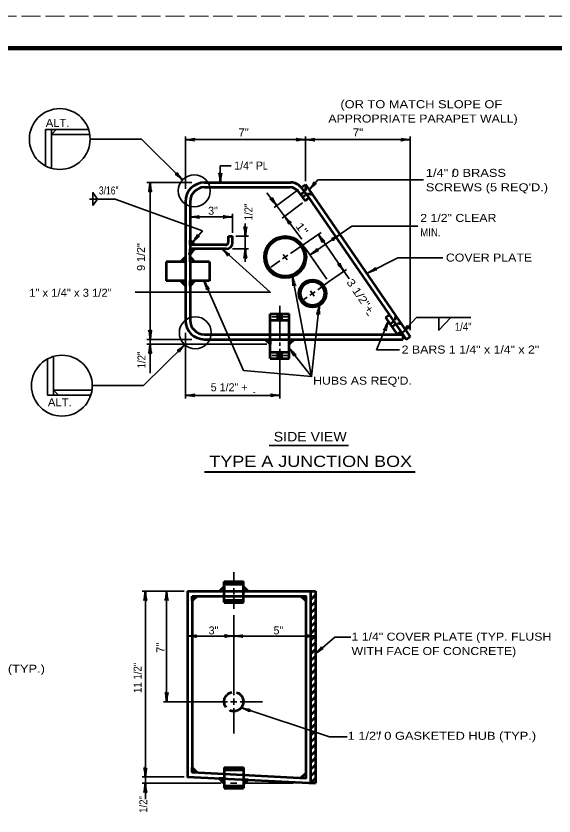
# Model space of a CAD drawing. Extents: x -1 to 679, y 0 to 440.
# Drawn here: x 229.6 to 397.8, y 190.4 to 440.4 of the extents above; entities that cross this region are included whole.
import ezdxf
from ezdxf.enums import TextEntityAlignment as Align

# ---------------------------------------------------------------- set-up
doc = ezdxf.new("R2010")
doc.units = 0
doc.header["$PDMODE"] = 32
doc.header["$PDSIZE"] = 0.5
doc.linetypes.add('LONG_DASHED', pattern=[7.5, 6, -1.5])
doc.linetypes.add('SHORT_DASHED', pattern=[2.7, 1.5, -1.2])
doc.layers.add('1', color=7, linetype='Continuous', lineweight=53)
doc.layers.add('61', color=7, linetype='Continuous', lineweight=35)

msp = doc.modelspace()

# ---------------------------------------------------------------- linework, layer by layer
at = {"layer": '1', "lineweight": 35}
for p, q in [((238.782, 404.893), (238.782, 393.562)), ((240.64, 404.893), (238.782, 404.893)), ((252.64, 403.393), (240.64, 403.393)), ((282.515, 386.364), (282.515, 402.759)), ((320.065, 388.759), (320.065, 402.759)), ((352.823, 342.25), (352.823, 402.759)), ((284.515, 388.364), (270.515, 388.364)), ((271.515, 388.364), (271.515, 339.364)), ((310.24, 380.571), (317.908, 386.18)), ((312.741, 377.253), (319.129, 382.067)), ((297.265, 377.614), (284.015, 377.614)), ((297.265, 372.614), (297.265, 378.614)), ((284.711, 369.667), (287.846, 373.294)), ((315.384, 366.197), (324.923, 372.761)), ((321.502, 365.743), (334.578, 374.741)), ((334.578, 374.741), (355.163, 374.741)), ((298.265, 371.614), (302.265, 371.614)), ((324.099, 372.195), (333.707, 358.234)), ((297.265, 367.614), (302.265, 367.614)), ((319.89, 368.084), (326.726, 358.152)), ((312.913, 364.496), (314.56, 365.63)), ((314.346, 364.254), (313.135, 365.862)), ((309.221, 361.956), (312.089, 363.93)), ((327.293, 357.328), (332.892, 361.181)), ((321.951, 327.71), (316.014, 358.975)), ((323.883, 354.848), (327.293, 357.328)), ((319.593, 351.858), (320.606, 352.555)), ((321.429, 353.122), (323.077, 354.256)), ((322.82, 352.865), (321.686, 354.513)), ((321.951, 327.71), (324.353, 349.989)), ((312.015, 339.364), (312.015, 349.864)), ((309.515, 346.364), (314.515, 346.364)), ((311.015, 346.864), (313.015, 346.864)), ((311.015, 345.864), (313.015, 345.864)), ((350.235, 341.27), (354.799, 346.197)), ((354.799, 346.197), (371.799, 346.197)), ((282.515, 341.364), (282.515, 320.864)), ((282.333, 337.658), (269.457, 324.936)), ((284.515, 339.364), (270.515, 339.364)), ((308.015, 337.864), (270.515, 337.864)), ((312.015, 337.364), (312.015, 338.364)), ((312.015, 320.864), (312.015, 336.364)), ((239.455, 321.936), (239.455, 333.267)), ((309.515, 334.364), (314.515, 334.364)), ((310.015, 333.364), (314.015, 333.364)), ((311.015, 334.864), (313.015, 334.864)), ((311.015, 333.864), (313.015, 333.864)), ((253.313, 323.436), (241.313, 323.436)), ((269.457, 324.936), (253.457, 324.936)), ((241.313, 321.936), (239.455, 321.936)), ((282.515, 321.864), (312.015, 321.864)), ((308.726, 306.159), (333.493, 306.159)), ((297.66, 266.653), (297.66, 262.637)), ((282.16, 260.653), (269.007, 260.653)), ((276.655, 226.153), (276.655, 260.653)), ((297.66, 261.653), (297.66, 259.653)), ((297.66, 258.679), (297.66, 255.153)), ((297.66, 253.153), (297.66, 228.175)), ((297.66, 246.653), (283.16, 246.653)), ((297.66, 246.653), (323.16, 246.653)), ((295.655, 226.153), (275.655, 226.153)), ((298.66, 226.153), (296.66, 226.153)), ((297.66, 227.153), (297.66, 225.153)), ((306.655, 226.153), (299.655, 226.153)), ((297.66, 224.175), (297.66, 216.175)), ((282.16, 202.653), (269.007, 202.653)), ((293.66, 200.653), (269.007, 200.653)), ((298.66, 200.653), (296.66, 200.653)), ((316.306, 200.653), (301.66, 200.653))]:
    msp.add_line(p, q, dxfattribs=at)
at = {"layer": '1'}
for p, q in [((288.515, 388.364), (315.52, 388.364)), ((318.715, 386.771), (320.065, 387.759)), ((320.065, 387.759), (352.804, 340.182)), ((288.515, 386.864), (315.271, 386.864)), ((317.667, 385.669), (319.928, 382.669)), ((318.715, 386.771), (321.126, 383.572)), ((319.928, 382.669), (321.126, 383.572)), ((321.126, 383.572), (350.515, 340.864)), ((282.515, 382.364), (282.515, 366.114)), ((296.015, 369.864), (296.015, 371.614)), ((296.015, 371.614), (297.265, 371.614)), ((297.265, 369.614), (297.265, 371.614)), ((295.015, 368.864), (284.015, 368.864)), ((295.265, 367.614), (284.015, 367.614)), ((284.015, 363.614), (284.015, 367.614)), ((282.515, 366.114), (282.515, 363.614)), ((282.515, 363.614), (276.515, 363.614)), ((276.515, 363.614), (276.515, 357.614)), ((282.515, 364.781), (282.515, 364.614)), ((282.515, 363.614), (282.515, 357.614)), ((284.015, 364.614), (284.015, 364.897)), ((290.015, 363.614), (284.015, 363.614)), ((284.015, 363.614), (284.015, 357.614)), ((290.015, 363.614), (290.015, 357.614)), ((282.515, 357.614), (276.515, 357.614)), ((282.515, 357.614), (282.515, 345.364)), ((290.015, 357.614), (284.015, 357.614)), ((309.015, 347.364), (315.015, 347.364)), ((309.015, 340.864), (309.015, 347.364)), ((309.015, 345.364), (315.015, 345.364)), ((345.048, 346.161), (346.248, 347.065)), ((345.048, 346.161), (348.694, 340.864)), ((288.515, 340.864), (350.515, 340.864)), ((350.515, 340.864), (350.515, 339.364)), ((350.515, 340.864), (351.569, 339.332)), ((351.569, 339.332), (352.823, 340.25)), ((318.962, 339.364), (350.515, 339.364)), ((309.015, 335.364), (315.015, 335.364)), ((309.015, 333.364), (315.015, 333.364)), ((294.66, 263.653), (300.66, 263.653)), ((294.66, 262.903), (300.66, 262.903)), ((300.66, 260.653), (300.66, 263.653)), ((321.66, 260.125), (322.188, 260.653)), ((323.16, 260.653), (323.16, 200.653)), ((284.66, 259.153), (320.16, 259.153)), ((284.66, 259.153), (284.66, 204.079)), ((294.66, 257.903), (300.66, 257.903)), ((320.16, 259.153), (320.16, 202.304)), ((321.66, 258.003), (323.16, 259.503)), ((294.66, 257.153), (300.66, 257.153)), ((321.66, 255.882), (323.16, 257.382)), ((321.66, 253.761), (323.16, 255.261)), ((321.66, 251.639), (323.16, 253.139)), ((321.66, 249.518), (323.16, 251.018)), ((321.66, 247.397), (323.16, 248.897)), ((321.66, 245.275), (323.16, 246.775)), ((321.66, 243.154), (323.16, 244.654)), ((321.66, 241.033), (323.16, 242.533)), ((321.66, 238.911), (323.16, 240.411)), ((321.66, 236.79), (323.16, 238.29)), ((321.66, 234.669), (323.16, 236.169)), ((321.66, 232.547), (323.16, 234.047)), ((321.66, 230.426), (323.16, 231.926)), ((321.66, 228.305), (323.16, 229.805)), ((321.66, 226.183), (323.16, 227.683)), ((321.66, 224.062), (323.16, 225.562)), ((321.66, 221.941), (323.16, 223.441)), ((321.66, 219.82), (323.16, 221.32)), ((321.66, 217.698), (323.16, 219.198)), ((321.66, 215.577), (323.16, 217.077)), ((321.66, 213.456), (323.16, 214.956)), ((321.66, 211.334), (323.16, 212.834)), ((321.66, 209.213), (323.16, 210.713)), ((321.66, 207.092), (323.16, 208.592)), ((294.66, 205.592), (300.66, 205.592)), ((321.66, 204.97), (323.16, 206.47)), ((284.66, 204.079), (320.16, 202.304)), ((294.66, 204.842), (300.66, 204.842)), ((321.66, 202.849), (323.16, 204.349)), ((294.66, 199.842), (300.66, 199.842)), ((294.66, 199.092), (300.66, 199.092))]:
    msp.add_line(p, q, dxfattribs=at)
at = {"layer": '1', "lineweight": 40}
msp.add_line((288.491, 297.936), (354.359, 297.936), dxfattribs=at)
at = {"layer": '1', "lineweight": 35}
for points in [[(252.282, 404.893), (240.64, 404.893), (240.64, 392.811)], [(281.66, 389.171), (268.784, 401.893), (252.784, 401.893)], [(282.515, 401.759), (320.065, 401.759), (352.823, 401.759)], [(293.44, 388.364), (293.44, 393.57), (296.843, 393.57)], [(321.197, 386.114), (323.934, 389.224), (356.949, 389.224)], [(308.038, 385.155), (311.048, 381.162), (313.539, 377.855), (318.956, 370.668)], [(287.846, 373.294), (260.595, 383.213), (252.595, 383.213)], [(301.265, 375.614), (301.265, 371.614), (301.265, 367.614), (301.265, 363.614)], [(293.982, 367.614), (309.04, 354.064), (266.816, 354.064)], [(339.636, 360.131), (348.902, 364.829), (363.034, 364.829)], [(288.399, 357.614), (300.734, 329.599), (321.951, 327.71), (315.015, 336.632)], [(361.799, 346.197), (361.799, 342.197), (365.547, 346.197)], [(345.94, 344.865), (342.28, 336.1), (349.445, 336.1)], [(271.515, 339.364), (271.515, 337.864), (271.515, 328.811)], [(252.955, 321.936), (241.313, 321.936), (241.313, 334.018)], [(270.007, 260.653), (270.007, 202.653), (270.007, 200.653), (270.007, 195.653)], [(323.16, 241.132), (329.224, 246.279), (334.261, 246.279)], [(299.999, 224.302), (327.546, 215.117), (333.142, 215.117)]]:
    msp.add_lwpolyline(points, dxfattribs=at)
for points in [[(240.64, 404.893), (242.14, 404.893), (240.64, 403.393)], [(253.595, 381.213), (253.595, 385.213), (255.095, 383.213)], [(241.313, 321.936), (242.813, 321.936), (241.313, 323.436)]]:
    msp.add_lwpolyline(points, close=True, dxfattribs=at)
at = {"layer": '1', "linetype": 'SHORT_DASHED'}
for points in [[(318.496, 384.568), (320.112, 385.786), (320.338, 387.363)], [(319.079, 383.763), (320.741, 384.917), (322.309, 384.638)], [(346.45, 344.117), (348.066, 345.334), (348.271, 346.764)], [(347.033, 343.311), (348.695, 344.465), (350.013, 344.231)]]:
    msp.add_lwpolyline(points, dxfattribs=at)
at = {"layer": '1'}
for points in [[(284.015, 382.364), (284.015, 368.864), (284.015, 367.614)], [(284.015, 358.614), (284.015, 357.614), (284.015, 345.364)], [(315.015, 333.364), (315.015, 339.364), (315.015, 347.364)], [(309.015, 333.364), (309.015, 339.364), (309.015, 340.864)], [(288.515, 339.364), (309.015, 339.364), (315.015, 339.364), (318.962, 339.364)], [(294.66, 257.153), (294.66, 260.653), (294.66, 263.653)], [(283.16, 260.653), (294.66, 260.653), (293.16, 260.653), (294.66, 262.153), (294.66, 260.653), (300.66, 260.653)], [(283.16, 260.653), (283.16, 202.653), (323.16, 200.653)], [(300.66, 257.153), (300.66, 260.653), (323.16, 260.653)], [(321.66, 260.653), (321.66, 200.728), (323.16, 202.228)], [(294.66, 205.592), (294.66, 202.092), (294.66, 199.092)], [(300.66, 205.592), (300.66, 202.092), (300.66, 199.092)]]:
    msp.add_lwpolyline(points, dxfattribs=at)
for points in [[(284.015, 368.864), (284.015, 370.364), (285.515, 368.864)], [(284.015, 367.614), (285.515, 367.614), (284.015, 366.114)], [(281.015, 363.614), (282.515, 365.114), (282.515, 363.614)], [(284.015, 363.614), (284.015, 365.114), (285.515, 363.614)], [(281.015, 357.614), (282.515, 357.614), (282.515, 356.114)], [(284.015, 357.614), (285.515, 357.614), (284.015, 356.114)], [(348.694, 340.864), (349.893, 341.767), (350.515, 340.864)], [(307.515, 339.364), (309.015, 339.364), (309.015, 337.864)], [(315.015, 339.364), (316.515, 339.364), (315.015, 337.864)], [(300.66, 262.153), (302.16, 260.653), (300.66, 260.653)], [(284.66, 259.153), (286.16, 259.153), (284.66, 257.653)], [(318.66, 259.153), (320.16, 259.153), (320.16, 257.653)], [(284.66, 205.579), (286.158, 204.005), (284.66, 204.079)], [(318.661, 202.379), (320.16, 203.804), (320.16, 202.304)], [(294.624, 202.11), (293.124, 202.11), (294.624, 200.61)], [(300.677, 200.237), (302.177, 201.737), (300.677, 201.737)]]:
    msp.add_lwpolyline(points, close=True, dxfattribs=at)
at = {"layer": '1', "lineweight": 35}
for centre, radius in [((243.25, 401.945), 9.5), ((285.313, 385.757), 5), ((285.635, 341.432), 5), ((243.923, 324.884), 9.5)]:
    msp.add_circle(centre, radius, dxfattribs=at)
at = {"layer": '1'}
for centre, radius in [((313.736, 365.063), 6.5), ((313.736, 365.096), 6), ((322.256, 353.685), 4.25), ((322.264, 353.72), 3.75)]:
    msp.add_circle(centre, radius, dxfattribs=at)
at = {"layer": '1', "linetype": 'LONG_DASHED'}
msp.add_circle((297.655, 226.175), 3, dxfattribs=at)
at = {"layer": '1'}
for centre, radius, start, end in [((288.515, 382.364), 6, 90, 180), ((315.52, 384.364), 4, 37.00042, 90), ((288.515, 382.364), 4.5, 90, 180), ((315.271, 383.864), 3, 36.99999, 90), ((295.015, 369.864), 1, 270, 0), ((295.265, 369.614), 2, 270, 0), ((288.515, 345.364), 6, 180, 270), ((288.515, 345.364), 4.5, 180, 270)]:
    msp.add_arc(centre, radius, start, end, dxfattribs=at)
at = {"layer": '1', "lineweight": 40}
for centre, major_axis, ratio, start_param, end_param in [((283.635, 401.547), (-1.756, 0.176), 0.07063, 3.1407148, 5.41811), ((283.635, 401.547), (-1.756, 0.176), 0.07063, 3.1407148, 5.41811), ((283.606, 402.035), (-1.786, -0.156), 0.122415, 0.8963533, 3.1415927), ((283.606, 402.035), (-1.786, -0.156), 0.122415, 0.8963533, 3.1415927), ((318.974, 401.483), (1.786, 0.156), 0.122415, 0.8963533, 3.1415927), ((318.974, 401.483), (1.786, 0.156), 0.122415, 0.8963533, 3.1415927), ((318.945, 401.971), (1.756, -0.176), 0.07063, 3.1407148, 5.41811), ((318.945, 401.971), (1.756, -0.176), 0.07063, 3.1407148, 5.41811), ((321.156, 402.035), (-1.786, -0.156), 0.122415, 0.8963533, 3.1415927), ((321.156, 402.035), (-1.786, -0.156), 0.122415, 0.8963533, 3.1415927), ((321.186, 401.547), (-1.756, 0.176), 0.07063, 3.1407148, 5.41811), ((321.186, 401.547), (-1.756, 0.176), 0.07063, 3.1407148, 5.41811), ((351.732, 401.483), (1.786, 0.156), 0.122415, 0.8963533, 3.1415927), ((351.702, 401.971), (1.756, -0.176), 0.07063, 3.1407148, 5.41811), ((280.689, 389.741), (1.38, -1.144), 0.122415, 0.8963533, 3.1415927), ((281.011, 390.109), (-1.126, 1.359), 0.07063, 6.2823074, 8.5597026), ((293.164, 389.455), (0.156, -1.786), 0.122415, 0.8963533, 3.1415927), ((293.652, 389.484), (-0.176, -1.756), 0.07063, 3.1407148, 5.41811), ((271.303, 387.243), (0.176, 1.756), 0.07063, 3.1407148, 5.41811), ((271.791, 387.273), (-0.156, 1.786), 0.122415, 0.8963533, 3.1415927), ((321.711, 387.116), (-1.062, -1.444), 0.122415, 0.8963533, 3.1415927), ((322.096, 386.815), (1.292, 1.203), 0.07063, 6.2823074, 8.5597026), ((310.17, 381.867), (1.199, -1.332), 0.122415, 0.8963533, 3.1415927), ((310.17, 381.867), (1.199, -1.332), 0.122415, 0.8963533, 3.1415927), ((310.542, 382.184), (-0.917, 1.508), 0.07063, 6.2823074, 8.5597026), ((310.542, 382.184), (-0.917, 1.508), 0.07063, 6.2823074, 8.5597026), ((285.135, 377.402), (-1.756, 0.176), 0.07063, 3.1407148, 5.41811), ((285.135, 377.402), (-1.756, 0.176), 0.07063, 3.1407148, 5.41811), ((285.106, 377.89), (-1.786, -0.156), 0.122415, 0.8963533, 3.1415927), ((285.106, 377.89), (-1.786, -0.156), 0.122415, 0.8963533, 3.1415927), ((296.174, 377.338), (1.786, 0.156), 0.122415, 0.8963533, 3.1415927), ((296.174, 377.338), (1.786, 0.156), 0.122415, 0.8963533, 3.1415927), ((296.144, 377.825), (1.756, -0.176), 0.07063, 3.1407148, 5.41811), ((296.144, 377.825), (1.756, -0.176), 0.07063, 3.1407148, 5.41811), ((314.045, 376.833), (0.917, -1.508), 0.07063, 6.2823074, 8.5597026), ((314.045, 376.833), (0.917, -1.508), 0.07063, 6.2823074, 8.5597026), ((314.417, 377.15), (-1.199, 1.332), 0.122415, 0.8963533, 3.1415927), ((314.417, 377.15), (-1.199, 1.332), 0.122415, 0.8963533, 3.1415927), ((300.988, 372.705), (0.156, -1.786), 0.122415, 0.8963533, 3.1415927), ((300.988, 372.705), (0.156, -1.786), 0.122415, 0.8963533, 3.1415927), ((301.476, 372.734), (-0.176, -1.756), 0.07063, 3.1407148, 5.41811), ((301.476, 372.734), (-0.176, -1.756), 0.07063, 3.1407148, 5.41811), ((285.216, 370.673), (-1.05, -1.453), 0.122415, 0.8963533, 3.1415927), ((285.604, 370.377), (1.281, 1.214), 0.07063, 6.2823074, 8.5597026), ((324.56, 371.152), (-0.851, 1.547), 0.07063, 3.1407148, 5.41811), ((324.56, 371.152), (-0.851, 1.547), 0.07063, 3.1407148, 5.41811), ((324.946, 371.452), (-1.141, 1.383), 0.122415, 0.8963533, 3.1415927), ((324.946, 371.452), (-1.141, 1.383), 0.122415, 0.8963533, 3.1415927), ((329.765, 371.686), (-1.547, -0.851), 0.07063, 6.2823074, 8.5597026), ((330.066, 371.301), (1.383, 1.141), 0.122415, 0.8963533, 3.1415927), ((294.674, 366.707), (1.188, -1.305), 0.07063, 6.2823074, 8.5597026), ((294.978, 367.089), (-1.432, 1.078), 0.122415, 0.8963533, 3.1415927), ((301.053, 366.493), (0.176, 1.756), 0.07063, 3.1407148, 5.41811), ((301.541, 366.523), (-0.156, 1.786), 0.122415, 0.8963533, 3.1415927), ((322.244, 366.589), (-1.383, -1.141), 0.122415, 0.8963533, 3.1415927), ((322.244, 366.589), (-1.383, -1.141), 0.122415, 0.8963533, 3.1415927), ((322.545, 366.204), (1.547, 0.851), 0.07063, 6.2823074, 8.5597026), ((322.545, 366.204), (1.547, 0.851), 0.07063, 6.2823074, 8.5597026), ((331.222, 361.357), (1.141, -1.383), 0.122415, 0.8963533, 3.1415927), ((331.222, 361.357), (1.141, -1.383), 0.122415, 0.8963533, 3.1415927), ((331.608, 361.658), (0.851, -1.547), 0.07063, 3.1407148, 5.41811), ((331.608, 361.658), (0.851, -1.547), 0.07063, 3.1407148, 5.41811), ((340.485, 360.871), (-1.522, -0.947), 0.122415, 0.8963533, 3.1415927), ((340.731, 360.449), (-1.646, -0.638), 0.07063, 3.1407148, 5.41811), ((288.657, 356.503), (0.547, -1.678), 0.07063, 6.2823074, 8.5597026), ((288.657, 356.503), (0.547, -1.678), 0.07063, 6.2823074, 8.5597026), ((289.091, 356.727), (-0.863, 1.571), 0.122415, 0.8963533, 3.1415927), ((289.091, 356.727), (-0.863, 1.571), 0.122415, 0.8963533, 3.1415927), ((316.015, 357.835), (-0.155, 1.758), 0.07063, 3.1407148, 5.41811), ((316.015, 357.835), (-0.155, 1.758), 0.07063, 3.1407148, 5.41811), ((316.489, 357.955), (-0.487, 1.725), 0.122415, 0.8963533, 3.1415927), ((316.489, 357.955), (-0.487, 1.725), 0.122415, 0.8963533, 3.1415927), ((324.023, 348.898), (-0.363, -1.728), 0.07063, 6.2823074, 8.5597026), ((324.023, 348.898), (-0.363, -1.728), 0.07063, 6.2823074, 8.5597026), ((324.511, 348.874), (0.036, 1.792), 0.122415, 0.8963533, 3.1415927), ((324.511, 348.874), (0.036, 1.792), 0.122415, 0.8963533, 3.1415927), ((345.313, 343.913), (-0.839, -1.553), 0.07063, 6.2823074, 8.5597026), ((345.775, 343.752), (0.544, 1.708), 0.122415, 0.8963533, 3.1415927), ((350.774, 342.259), (-1.099, -1.416), 0.122415, 0.8963533, 3.1415927), ((350.774, 342.259), (-1.099, -1.416), 0.122415, 0.8963533, 3.1415927), ((351.152, 341.949), (-1.323, -1.169), 0.07063, 3.1407148, 5.41811), ((351.152, 341.949), (-1.323, -1.169), 0.07063, 3.1407148, 5.41811), ((271.238, 340.455), (0.156, -1.786), 0.122415, 0.8963533, 3.1415927), ((271.726, 340.484), (-0.176, -1.756), 0.07063, 3.1407148, 5.41811), ((271.303, 336.743), (0.176, 1.756), 0.07063, 3.1407148, 5.41811), ((271.303, 336.743), (0.176, 1.756), 0.07063, 3.1407148, 5.41811), ((271.791, 336.773), (-0.156, 1.786), 0.122415, 0.8963533, 3.1415927), ((271.791, 336.773), (-0.156, 1.786), 0.122415, 0.8963533, 3.1415927), ((281.362, 337.088), (1.38, 1.144), 0.122415, 3.1415927, 5.386832), ((281.684, 336.72), (-1.126, -1.359), 0.07063, 4.006668, 6.2840632), ((315.535, 335.617), (0.939, -1.494), 0.07063, 6.2823074, 8.5597026), ((315.535, 335.617), (0.939, -1.494), 0.07063, 6.2823074, 8.5597026), ((315.903, 335.94), (-1.219, 1.314), 0.122415, 0.8963533, 3.1415927), ((315.903, 335.94), (-1.219, 1.314), 0.122415, 0.8963533, 3.1415927), ((283.635, 321.652), (-1.756, 0.176), 0.07063, 3.1407148, 5.41811), ((283.606, 322.14), (-1.786, -0.156), 0.122415, 0.8963533, 3.1415927), ((310.924, 321.588), (1.786, 0.156), 0.122415, 0.8963533, 3.1415927), ((310.894, 322.075), (1.756, -0.176), 0.07063, 3.1407148, 5.41811), ((269.795, 259.532), (0.176, 1.756), 0.07063, 3.1407148, 5.41811), ((269.795, 259.532), (0.176, 1.756), 0.07063, 3.1407148, 5.41811), ((270.283, 259.561), (-0.156, 1.786), 0.122415, 0.8963533, 3.1415927), ((270.283, 259.561), (-0.156, 1.786), 0.122415, 0.8963533, 3.1415927), ((276.443, 259.532), (0.176, 1.756), 0.07063, 3.1407148, 5.41811), ((276.443, 259.532), (0.176, 1.756), 0.07063, 3.1407148, 5.41811), ((276.931, 259.561), (-0.156, 1.786), 0.122415, 0.8963533, 3.1415927), ((276.931, 259.561), (-0.156, 1.786), 0.122415, 0.8963533, 3.1415927), ((284.28, 246.441), (-1.756, 0.176), 0.07063, 3.1407148, 5.41811), ((284.28, 246.441), (-1.756, 0.176), 0.07063, 3.1407148, 5.41811), ((284.251, 246.929), (-1.786, -0.156), 0.122415, 0.8963533, 3.1415927), ((284.251, 246.929), (-1.786, -0.156), 0.122415, 0.8963533, 3.1415927), ((296.568, 246.376), (1.786, 0.156), 0.122415, 0.8963533, 3.1415927), ((296.539, 246.864), (1.756, -0.176), 0.07063, 3.1407148, 5.41811), ((298.78, 246.441), (-1.756, 0.176), 0.07063, 3.1407148, 5.41811), ((298.78, 246.441), (-1.756, 0.176), 0.07063, 3.1407148, 5.41811), ((298.751, 246.929), (-1.786, -0.156), 0.122415, 0.8963533, 3.1415927), ((298.751, 246.929), (-1.786, -0.156), 0.122415, 0.8963533, 3.1415927), ((322.068, 246.376), (1.786, 0.156), 0.122415, 0.8963533, 3.1415927), ((322.068, 246.376), (1.786, 0.156), 0.122415, 0.8963533, 3.1415927), ((322.039, 246.864), (1.756, -0.176), 0.07063, 3.1407148, 5.41811), ((322.039, 246.864), (1.756, -0.176), 0.07063, 3.1407148, 5.41811), ((323.813, 242.049), (-1.26, -1.275), 0.122415, 0.8963533, 3.1415927), ((323.813, 242.049), (-1.26, -1.275), 0.122415, 0.8963533, 3.1415927), ((324.151, 241.696), (1.453, 1.003), 0.07063, 6.2823074, 8.5597026), ((324.151, 241.696), (1.453, 1.003), 0.07063, 6.2823074, 8.5597026), ((276.379, 227.244), (0.156, -1.786), 0.122415, 0.8963533, 3.1415927), ((276.866, 227.273), (-0.176, -1.756), 0.07063, 3.1407148, 5.41811), ((300.995, 223.747), (1.611, -0.722), 0.07063, 6.2823074, 8.5597026), ((300.995, 223.747), (1.611, -0.722), 0.07063, 6.2823074, 8.5597026), ((301.121, 224.219), (-1.743, 0.417), 0.122415, 0.8963533, 3.1415927), ((301.121, 224.219), (-1.743, 0.417), 0.122415, 0.8963533, 3.1415927), ((269.73, 203.744), (0.156, -1.786), 0.122415, 0.8963533, 3.1415927), ((269.73, 203.744), (0.156, -1.786), 0.122415, 0.8963533, 3.1415927), ((270.218, 203.773), (-0.176, -1.756), 0.07063, 3.1407148, 5.41811), ((270.218, 203.773), (-0.176, -1.756), 0.07063, 3.1407148, 5.41811), ((269.795, 199.532), (0.176, 1.756), 0.07063, 3.1407148, 5.41811), ((270.283, 199.561), (-0.156, 1.786), 0.122415, 0.8963533, 3.1415927)]:
    msp.add_ellipse(centre, major_axis=major_axis, ratio=ratio, start_param=start_param, end_param=end_param, dxfattribs=at)
at = {"layer": '1'}
msp.add_point((284.015, 366.114), dxfattribs=at)
at = {"layer": '61', "linetype": 'LONG_DASHED', "lineweight": 13}
msp.add_line((-1.237, 440.398), (678.783, 440.398), dxfattribs=at)
at = {"layer": '61', "lineweight": 158}
msp.add_lwpolyline([(667.803, 430.398), (28.763, 430.398), (28.763, 10.378)], dxfattribs=at)

# ---------------------------------------------------------------- texts
at = {"layer": '1'}
for s, width, p in [('(OR TO MATCH SLOPE OF', 1.2, (356.277, 411.592)), (' APPROPRIATE PARAPET WALL)', 1.15, (356.277, 407.092))]:
    msp.add_text(s, height=2.5, dxfattribs=dict(at, width=width)).set_placement(p, align=Align.CENTER)
for s, height, width, p in [('ALT.', 2.5, 1.05, (238.886, 405.75)), ('7"', 2.5, 1.05, (299.127, 402.79)), ('7"', 2.5, 1.05, (334.896, 402.79)), ('L', 2.5, 0.75, (306.792, 392.433)), ('1/4" 0 BRASS', 2.5, 1.2, (357.694, 390.131)), ("SCREWS (5 REQ'D.)", 2.5, 1.2, (357.694, 385.631)), ('3/16"', 2.5, 0.8, (255.48, 384.63)), ('2 1/2" CLEAR', 2.5, 1.15, (355.946, 376.049)), ('MIN.', 2.5, 0.9, (355.946, 371.549)), ('COVER PLATE', 2.5, 1.15, (363.972, 363.667)), ('1" x 1/4" x 3 1/2"', 2.5, 1.05, (233.69, 352.67)), ('1/4"', 2.5, 0.9, (366.748, 342.048)), ('2 BARS 1 1/4" x 1/4" x 2"', 2.5, 1.15, (350.149, 334.932)), ("HUBS AS REQ'D.", 2.5, 1.15, (322.469, 325.203)), ('ALT.', 2.5, 1.05, (239.558, 318.451)), ('SIDE VIEW', 3, 1.1, (310.147, 307.448)), ('TYPE A JUNCTION BOX', 3.5, 1.2, (290.026, 299.501)), ('1 1/4" COVER PLATE (TYP. FLUSH', 2.5, 1.15, (334.455, 245.225)), ('WITH FACE OF CONCRETE)', 2.5, 1.15, (334.455, 240.725)), ('1 1/2" 0 GASKETED HUB (TYP.)', 2.5, 1.2, (179.679, 235.199)), ('1 1/2" 0 GASKETED HUB (TYP.)', 2.5, 1.2, (333.236, 214.246))]:
    msp.add_text(s, height=height, dxfattribs=dict(at, width=width)).set_placement(p)
for s, p in [('1/4" P', (297.783, 392.433)), ('/', (365.871, 390.085)), ('3"', (289.637, 378.297)), ('5 1/2" +', (290.447, 323.141)), ('-', (303.477, 321.742)), ('3"', (289.794, 247.171)), ('5"', (310.074, 247.171)), ('/', (342.766, 214.246))]:
    msp.add_text(s, height=2.5, dxfattribs=at).set_placement(p)
for s, rotation, width, p in [('1/2"', 90, 0.9, (303.477, 376.529)), ('1"', 307.001, 1.25, (316.797, 374.709)), ('3 1/2"+', 304.535, 1.15, (332.75, 357.208)), ('-', 304.535, 1.65, (338.148, 347.364)), ('1/2"', 90, 0.9, (270.055, 330.284)), ('7"', 90, 1.05, (275.941, 241.406)), ('11 1/2"', 90, 0.9, (268.849, 228.879)), ('1/2"', 90, 0.9, (270.622, 191.409))]:
    msp.add_text(s, height=2.5, rotation=rotation, dxfattribs=dict(at, width=width)).set_placement(p)
msp.add_text('9 1/2"', height=2.5, rotation=90, dxfattribs=at).set_placement((269.908, 360.771))

doc.saveas('drawing.dxf')
